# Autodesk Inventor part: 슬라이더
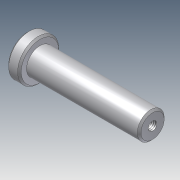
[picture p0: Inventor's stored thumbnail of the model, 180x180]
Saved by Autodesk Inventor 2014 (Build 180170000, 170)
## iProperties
Company: 한국ATC센터
Created: 2014-08
Part Number: 슬라이더
Document SubType Name: Modeling
Designer: KYOUNG IL JANG
Density: 1 g/cm^3
Material: 일반
Appearance: 기본값
Mass: 13.6925 g
Surface Area: 43.9337 cm^2
Volume: 13.6925 cm^3
Author: KYOUNG IL JANG
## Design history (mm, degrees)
sketch "스케치1"
  geometry: L1 (-7, 0)-(63, 0); L2 (63, 0)-(63, 7.5); L3 (63, 7.5)-(0, 7.5); L4 (-7, 0)-(-7, 11.5); L5 (-7, 11.5)-(0, 11.5); L6 (0, 11.5)-(0, 7.5); 1 further point
  constraints: 12 end point, 3 perpendicular, 2 horizontal, 2 point on line, 1 parallel
  dimensions: "d1" = 70 distance of L1.start L1.end; "d19" = 15 diameter of L3 L1; "d20" = 7 distance of L4.end L5.end; "d21" = 23 diameter of L5 L1
revolve "회전1" stored, may be unused: angle "d4" = 90 deg
chamfer "모따기1" distance "d16" = 1; stored, may be unused: second distance "d17" = 2, angle "d18" = 45 deg
hole "구멍2" diameter "d24" = 4.917; stored, may be unused: countersink angle "d28" = 90 deg, drill point angle "d30" = 118 deg; dims "d22" = 10, "d23" = 10, "d25" = 10, "d26" = 4, "d27" = 2, "d29" = 13
node "솔리드1"
